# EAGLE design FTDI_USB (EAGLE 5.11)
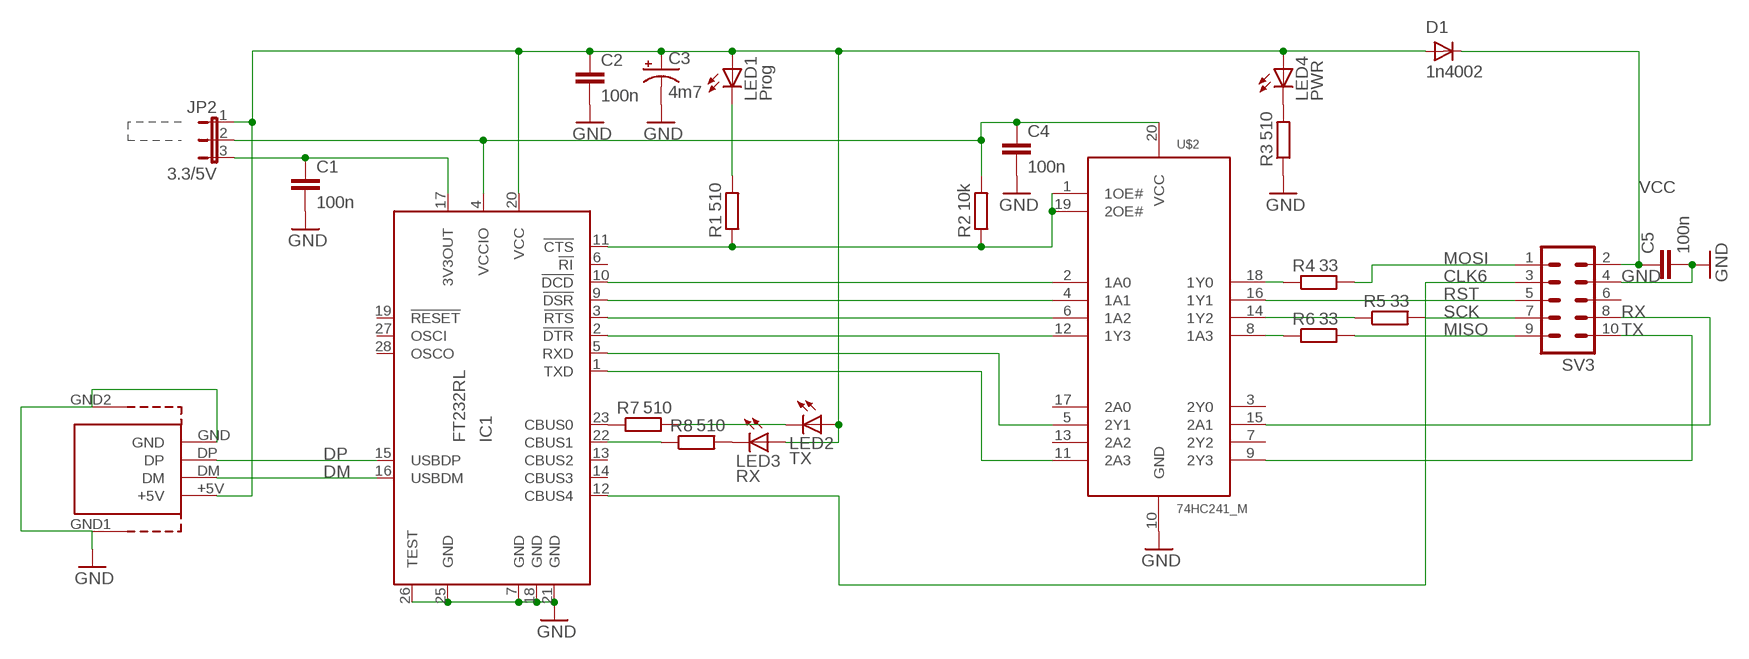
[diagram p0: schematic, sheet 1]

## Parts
C1  100n  C-EUC1206  [C1206]
C2  100n  C-EUC1206  [C1206]
C3  4m7  CPOL-USSMCD  [SMC_D]
C4  100n  C-EUC1206  [C1206]
C5  100n  C-EUC1206  [C1206]
D1  1n4002  GF1  [SMA-DO214AC]
IC1  FT232RL  [SSOP28]
JP2  3.3/5V  JP2E  [JP2]
LED1  Prog  LEDCHIPLED_1206  [CHIPLED_1206]
LED2  TX  LEDCHIPLED_1206  [CHIPLED_1206]
LED3  RX  LEDCHIPLED_1206  [CHIPLED_1206]
LED4  PWR  LEDCHIPLED_1206  [CHIPLED_1206]
R1  510  R-EU_M1206  [M1206]
R2  10k  R-EU_M1206  [M1206]
R3  510  R-EU_M1206  [M1206]
R4  33  R-EU_M1206  [M1206]
R5  33  R-EU_M1206  [M1206]
R6  33  R-EU_M1206  [M1206]
R7  510  R-EU_M1206  [M1206]
R8  510  R-EU_M1206  [M1206]
SV3  ML10  [ML10]
U$1  USB  [USB]
U$2  74HC241_M  [SO20W]

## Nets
CLK6: IC1.12(CBUS4) SV3.3
DM: IC1.16(USBDM) U$1.DM
DP: IC1.15(USBDP) U$1.DP
GND: C1.2 C2.2 C3.- C4.2 C5.2 IC1.7(GND) IC1.18(GND) IC1.21(GND) IC1.25(GND) IC1.26(TEST) R3.1 SV3.4 U$1.GND U$1.GND1 U$1.GND2 U$2.10(GND)
MISO: R6.2 SV3.9
MOSI: R4.2 SV3.1
N$1: IC1.10(!DCD) U$2.2(1A0)
N$2: IC1.9(!DSR) U$2.4(1A1)
N$3: IC1.3(!RTS) U$2.6(1A2)
N$4: IC1.2(!DTR) U$2.12(1Y3)
N$5: IC1.5(RXD) U$2.5(2Y1)
N$6: IC1.1(TXD) U$2.11(2A3)
N$7: IC1.11(!CTS) R1.1 R2.1 U$2.1(1OE#) U$2.19(2OE#)
N$8: C2.1 C3.+ D1.A IC1.20(VCC) JP2.1 LED1.A LED2.A LED3.A LED4.A U$1.+5V
N$9: C1.1 IC1.17(3V3OUT) JP2.3
N$10: C4.1 IC1.4(VCCIO) JP2.2 R2.2 U$2.20(VCC)
N$11: LED1.C R1.2
N$12: LED2.C R7.2
N$13: LED3.C R8.2
N$14: IC1.23(CBUS0) R7.1
N$15: IC1.22(CBUS1) R8.1
N$16: LED4.C R3.2
N$17: R6.1 U$2.8(1A3)
N$18: R5.1 U$2.14(1Y2)
N$19: R4.1 U$2.18(1Y0)
RST: SV3.5 U$2.16(1Y1)
RX: SV3.8 U$2.15(2A1)
SCK: R5.2 SV3.7
TX: SV3.10 U$2.9(2Y3)
VCC: C5.1 D1.K(C) SV3.2
Unconnected: IC1.6(!RI) IC1.13(CBUS2) IC1.14(CBUS3) IC1.19(!RESET) IC1.27(OSCI) IC1.28(OSCO) SV3.6 U$2.3(2Y0) U$2.7(2Y2) U$2.13(2A2) U$2.17(2A0)

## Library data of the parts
C1 C2 C4 C5 = resistor:C-EU: CAPACITOR, European symbol
C3 = rcl:CPOL-US: POLARIZED CAPACITOR, American symbol
D1 = diode:GF1: DIODE
IC1 = ftdichip_m:FT232R: Source: http://www.ftdichip.com/Documents/DataSheets/DS_FT232R_v104.pdf; MPN: FT232RL; OC_FARNELL: 1146032; OC_NEWARK: 91K9918
JP2 = jumper:JP2E: JUMPER
LED1-LED4 = led:LED: LED
R1-R8 = resistor:R-EU_: RESISTOR, European symbol
SV3 = con-ml:ML10: HARTING; OC_FARNELL: unknown; OC_NEWARK: unknown
U$1 = USB:USB
U$2 = 74xx-eu:74HC241_M

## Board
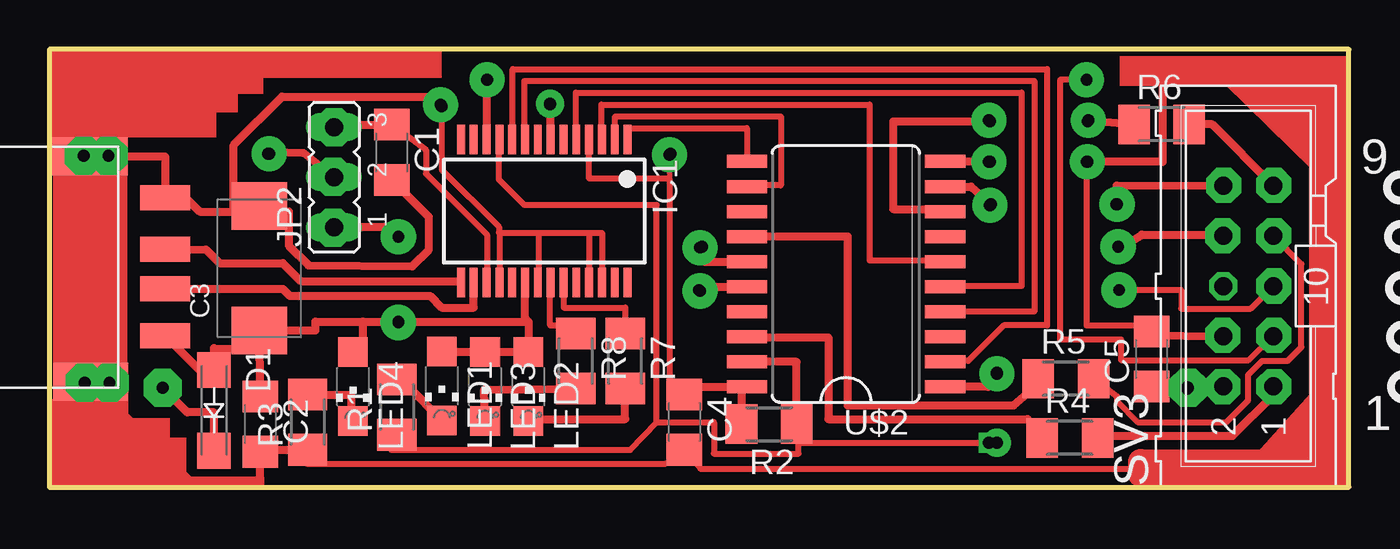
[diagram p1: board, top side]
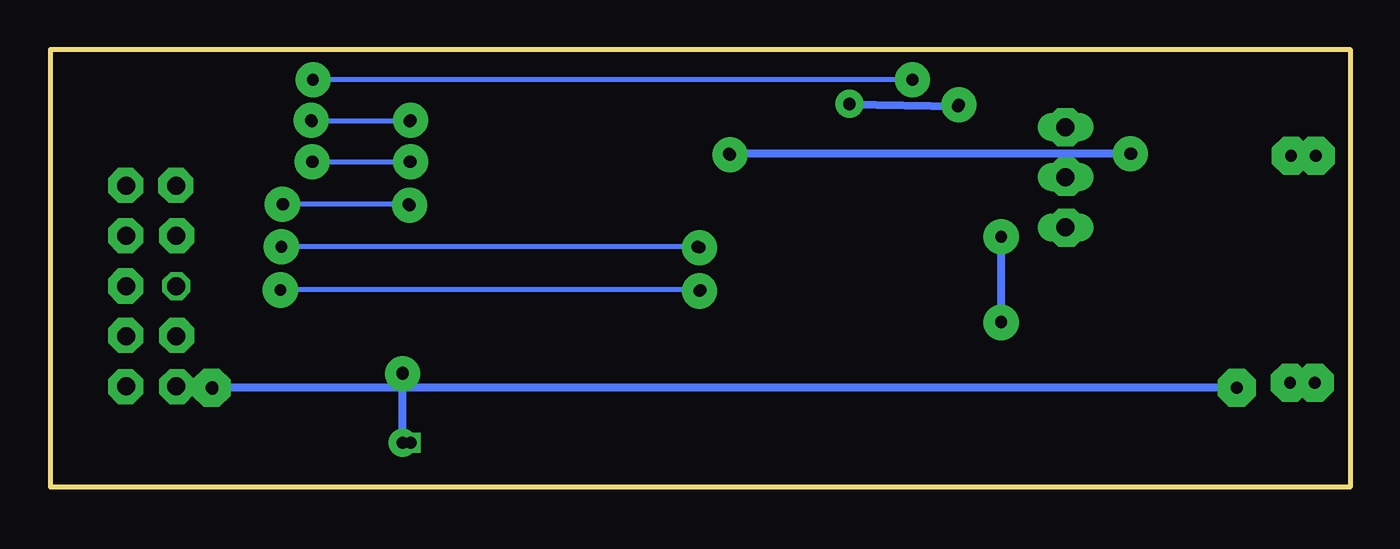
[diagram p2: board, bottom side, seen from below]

Size 65.9 x 22.2 mm. Coordinates in mm from the lower left corner, seen from the top.
Outline: 0,0 65.9,0 65.9,22.2 0,22.2 0,0
Copper layers (1*16): Top 0.035mm / dielectric 1.5mm / Bottom 0.035mm
Design rules "default": minimum track width 10mil, minimum drill 24mil, track to track 8mil, track to pad 8mil, pad to pad 8mil, via to via 8mil, smd to smd 8mil, copper to edge 40mil, drill to drill 8mil, minimum pad ring 10mil, minimum via ring 8mil, stop-mask expansion 4mil, vias tented up to drill 0mil, thermal gap 10mil

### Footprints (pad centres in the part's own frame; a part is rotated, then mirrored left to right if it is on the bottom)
C1206 = smd 1.6 x 1.8: 1 -1.4,0; 2 1.4,0
SMC_D = smd 2.4 x 2.8: + -3.15,0; - 3.15,0
SMA-DO214AC = smd 1.8 x 1.7: A -2.05,0; K 2.05,0
SSOP28 = smd 0.4 x 1.5: 1 -4.225,-3.625; 2 -3.575,-3.625; 3 -2.925,-3.625; 4 -2.275,-3.625; 5 -1.625,-3.625; 6 -0.975,-3.625; 7 -0.325,-3.625; 8 0.325,-3.625; 9 0.975,-3.625; 10 1.625,-3.625; 11 2.275,-3.625; 12 2.925,-3.625; 13 3.575,-3.625; 14 4.225,-3.625; 15 4.225,3.625; 16 3.575,3.625; 17 2.925,3.625; 18 2.275,3.625; 19 1.625,3.625; 20 0.975,3.625; 21 0.325,3.625; 22 -0.325,3.625; 23 -0.975,3.625; 24 -1.625,3.625; 25 -2.275,3.625; 26 -2.925,3.625; 27 -3.575,3.625; 28 -4.225,3.625
JP2 = drill 0.914 long: 1 -2.54,0; 2 0,0; 3 2.54,0
CHIPLED_1206 = smd 1.5 x 1.5: A 0,-1.75; C 0,1.75
M1206 = smd 1.6 x 2: 1 -1.4,0; 2 1.4,0
ML10 = drill 0.914 octagon: 1 -5.08,-1.27; 2 -5.08,1.27; 3 -2.54,-1.27; 4 -2.54,1.27; 5 0,-1.27; 6 0,1.27; 7 2.54,-1.27; 8 2.54,1.27; 9 5.08,-1.27; 10 5.08,1.27
USB = smd 2.54 x 1.27: +5V 6.78,-3.27; DM 6.78,-0.895; DP 6.78,1.11; GND 6.78,3.715 | smd 3.81 x 1.93: GND1 3.005,-5.61; GND2 2.97,5.82
SO20W = smd 0.66 x 2.032: 1 -5.715,-5.029; 2 -4.445,-5.029; 3 -3.175,-5.029; 4 -1.905,-5.029; 5 -0.635,-5.029; 6 0.635,-5.029; 7 1.905,-5.029; 8 3.175,-5.029; 9 4.445,-5.029; 10 5.715,-5.029; 11 5.715,5.029; 12 4.445,5.029; 13 3.175,5.029; 14 1.905,5.029; 15 0.635,5.029; 16 -0.635,5.029; 17 -1.905,5.029; 18 -3.175,5.029; 19 -4.445,5.029; 20 -5.715,5.029

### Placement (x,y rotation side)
C1  17.36,16.98 270 top
C2  10.7,3.2 270 top
C3  10.65,11.1 90 top
C4  32.2,3.3 270 top
C5  55.9,6.5 90 top
D1  8.35,3.9 270 top
IC1  25.1,14 180 top
JP2  14.44,15.72 90 top
LED1  19.9,5.14 180 top
LED2  24.3,5.1 180 top
LED3  22.1,5.1 180 top
LED4  15.4,5.1 180 top
R1  17.64,4.06 90 top
R2  36.5,3.2 180 top
R3  13.1,3.3 90 top
R4  51.75,2.5 0 top
R5  51.55,5.5 0 top
R6  56.4,18.4 0 top
R7  29.2,6.4 270 top
R8  26.7,6.4 270 top
SV3  60.8,10.2 90 top
U$1  -0.91,10.95 0 top
U$2  40.4,10.8 90 top

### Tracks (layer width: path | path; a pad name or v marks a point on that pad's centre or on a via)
CLK6  (via drill 0.6 pad 1.78)
  Top 0.254: IC1.12 22.2,18.02
  Top 0.305: SV3.3 60.82,6.45 54.35,6.45 54.35,7.5 51.25,7.5 51.25,20.65 v52.6,20.65
  Top 0.406: 22.2,18.02 v22.2,20.65
  Bottom 0.254: v22.2,20.65 v52.6,20.65
DM
  Top 0.406: U$1.DM 11.84,10.06 12.2,9.7 19.3,9.7 19.9,9.1 21.53,9.1 IC1.16
DP
  Top 0.254: U$1.DP 5.9,12.1
  Top 0.406: IC1.15 20.88,10.45 12.75,10.45 11.83,11.37 8.64,11.37 7.95,12.05 5.9,12.1
GND  (via drill 0.6, 0.6 pad 1.78)
  Top 0.254: IC1.25 27.4,10.77 27.4,12.9 | 24.8,10.77 IC1.21 | 25.4,18.12 IC1.7 | 31.25,1.2 C4.2 33,0.95 | R3.1 13.05,1.2 | 45.43,16.5 U$2.10 | v47.7,16.5 v47.65,16.5 | v52.65,16.5 v52.6,16.5 | 56.45,20.5 59.7,20.5 64.1,16.2 64.1,4.9 63.85,1.2 56.65,0.8 54.8,0.95 | 55.2,8.2 C5.2 | 9.35,13.97 10.7,13.97 | 7,14.6 5.94,14.6 U$1.GND | 10,2.4 10.9,1.5 10.9,2 C2.2 | 22.8,12.92 22.82,12.9
  Top 0.305: 24.8,12.9 27.38,12.9 IC1.25 | 27.4,12.9 28.03,12.9 IC1.26 | 24.8,12.9 24.8,10.77 | IC1.18 22.82,12.9 24.8,12.9 | 13.05,1.2 31.25,1.2 | v52.6,16.5 52.6,8.2 55.2,8.2 | 33,0.95 54.8,0.95 | 22.8,12.92 22.8,13.2 19.9,16.1 v19.9,19.3
  Top 0.406: 2.1,16.77 U$1.GND2 | 2.1,16.77 U$1.GND1 7.09,0.35 10.7,0.35 C2.2 11.1,1.8 11,1.9 R3.1 | 2.1,16.77 5.87,16.77 U$1.GND | C3.- 10.7,13.97 12.15,13.97 12.15,12.25 13.15,11.25 18.4,11.2 19.25,12.05 19.25,13.69 C1.2 | v25.4,19.4 25.4,18.12 | v19.9,19.3 19.9,19.8 11.8,19.8 9.35,17.35 9.35,13.97 7.63,13.97 7,14.6 | C5.2 55.53,7.7 SV3.4 | v47.65,16.5 45.43,16.5 | v52.65,16.5 56.45,16.5 56.45,20.5
  Bottom 0.254: v52.6,16.5 v47.7,16.5
  Bottom 0.406: v19.9,19.3 v25.4,19.4
MISO
  Top 0.406: R6.2 58.97,18.4 SV3.9
MOSI
  Top 0.254: 62.07,4.67 SV3.1 | R4.2 52.7,2.6
  Top 0.406: 62.07,4.67 60,2.6 52.7,2.6
N$1
  Top 0.254: IC1.10 23.5,18.02 | 45.43,6.4 U$2.2
  Top 0.305: 23.5,18.02 23.5,21.2 50.6,21.2 50.6,8.2 48.4,8.2 46.6,6.4 45.43,6.4
N$2
  Top 0.254: IC1.9 24.1,18.02 | U$2.4
  Top 0.305: 24.1,18.02 24.1,20.6 49.95,20.6 49.95,8.9 U$2.4
N$3
  Top 0.254: IC1.3 28,18.02 | 45.43,11.5 U$2.6
  Top 0.305: 28,18.02 28,19.4 41.6,19.4 41.6,11.5 45.43,11.5
N$4
  Top 0.254: IC1.2 28.7,18.02 | 35.37,15.3 U$2.12
  Top 0.305: 28.7,18.02 28.7,18.8 37.1,18.8 37.1,15.3 35.37,15.3
N$5
  Top 0.254: IC1.5 26.7,18.12 | 45.43,10.2 U$2.5
  Top 0.305: 26.7,18.12 26.7,20 49.3,20 49.3,10.2 45.43,10.2
N$6
  Top 0.254: 29.35,18.2 29.35,17.62 IC1.1
  Top 0.305: U$2.11 35.37,18.2 29.35,18.2
N$7  (via drill 0.6, 0.6 pad 1.42)
  Top 0.254: 22.8,17.98 IC1.11 | 38,2.25 R2.1 | 17.35,1.9 17.64,2.23 R1.1
  Top 0.305: 22.8,17.98 22.8,15.6 24.1,14.3 30.8,14.3 30.8,3.3 | 30.8,3.3 33.7,3.3 33.7,1.7 38,1.7 38,2.25 v48.05,2.25 | 30.8,3.3 29.45,1.9 17.35,1.9
  Top 0.406: U$2.19 37.9,6.35 R2.1 | U$2.1 47.6,5.09 v48.05,5.8
  Bottom 0.406: v48.05,5.8 v48.05,2.25 v47.65,2.25
N$8  (via drill 0.6, 0.6 pad 1.78)
  Top 0.254: D1.A 8.3,5.35 | U$1.+5V 5.8,7.62
  Top 0.406: 10.65,7 C2.1 | 10.65,7 C3.+ 13.5,7.95 13.5,8.4 15.9,8.4 | 5.87,8.05 U$1.+5V 7.61,5.95 D1.A 8.35,7.05 10.65,7 | 15.9,8.4 v17.7,8.4 24.3,8.4 | IC1.20 24.13,8.6 24.3,8.4 | LED4.A 15.9,6.85 15.9,8.4 | 24.3,8.4 LED2.A LED3.A 19.5,6.85 LED1.A | JP2.1 17.7,13.17 v17.7,12.7
  Bottom 0.406: v17.7,8.4 v17.7,12.7
N$9
  Top 0.254: 22.2,10.77 IC1.17
  Top 0.305: 22.2,10.77 22.2,12.8 19.1,15.9 19.1,17.1 17.36,18.4
  Top 0.406: JP2.3 14.44,18.38 C1.1 17.36,18.4
N$10  (via drill 0.6)
  Top 0.254: IC1.4 27.4,18.02 | 31.45,16 31.45,15.65 | 35.37,5.1 U$2.20 35.1,5.09 | 31.45,5.1 32.5,5.1 C4.1
  Top 0.305: v31.5,16.9 31.45,16 | 31.45,5.1 31.45,15.65 27.38,15.65 IC1.4
  Top 0.406: JP2.2 12.89,16.95 11.25,17 v11.1,16.9 | 32.5,5.1 35.37,5.1 | 35.1,5.09 R2.2
  Bottom 0.406: v11.1,16.9 v31.5,16.9
N$11
  Top 0.254: 18.24,5.06 R1.2
  Top 0.406: LED1.C 18.24,5.06
N$12
  Top 0.406: R7.2 29.2,3.45 24.1,3.45 LED2.C
N$13
  Top 0.406: LED3.C 22.05,4.95 R8.2
N$14
  Top 0.254: 26.1,10.73 IC1.23
  Top 0.305: 26.1,10.73 26.1,9.1 29.2,9.1 R7.1
N$15
  Top 0.254: 25.4,10.73 IC1.22
  Top 0.305: 25.4,10.73 25.4,8.2 27.2,8.2
  Top 0.406: 27.2,8.2 R8.1
N$16
  Top 0.254: 15.3,3.35 LED4.C
  Top 0.406: 15.3,3.35 15.3,4.7 R3.2
N$17  (via drill 0.6, 0.6 pad 1.78)
  Top 0.254: U$2.8 45.58,13.98 44.55,14.1 | v52.65,18.55 v52.7,18.6
  Top 0.406: 44.55,14.1 42.8,14.1 42.8,18.55 v47.7,18.55 | v52.7,18.6 R6.1
  Bottom 0.254: v47.7,18.55 v52.65,18.55
N$18
  Top 0.254: 50.15,5.25 R5.1
  Top 0.406: 50.15,5.25 48.9,4.15 40.5,4.15 40.5,12.7 U$2.14
N$19
  Top 0.406: U$2.18 35.37,7.6 39.5,7.6 39.5,3.45 49.6,3.45 R4.1
N$20  (via drill 0.6 pad 1.78)
  other vias: 11.15,16.9
N$21  (via drill 0.6 pad 1.78)
  other vias: 19.85,19.4
N$22  (via drill 0.6 pad 1.42)
  other vias: 25.4,19.45
N$23  (via drill 0.6 pad 1.78)
  other vias: 31.45,16.85
N$24  (via drill 0.6 pad 1.78)
  other vias: 17.7,8.35
N$25  (via drill 0.6 pad 1.78)
  other vias: 33,12.15
N$26  (via drill 0.6 pad 1.78)
  other vias: 33,9.95
N$27  (via drill 0.6 pad 1.78)
  other vias: 54.2,12.2
N$28  (via drill 0.6 pad 1.78)
  other vias: 54.25,10
N$29  (via drill 0.6 pad 1.78)
  other vias: 47.7,14.3
N$30  (via drill 0.6 pad 1.78)
  other vias: 54.15,14.35
N$31  (via drill 0.6 pad 1.78)
  other vias: 47.65,18.6
N$32  (via drill 0.6 pad 1.78)
  other vias: 48.05,5.75
N$34  (via drill 0.6 pad 1.78)
  other vias: 57.7,5
N$35  (via drill 0.7 pad 1.78)
  other vias: 59.55,15.3
N$36  (via drill 0.7 pad 1.78)
  other vias: 62.1,15.3
N$37  (via drill 0.7 pad 1.78)
  other vias: 62.1,12.75
N$38  (via drill 0.7 pad 1.78)
  other vias: 59.5,12.75
N$39  (via drill 0.7 pad 1.78)
  other vias: 62.1,10.2
N$40  (via drill 0.7 pad 1.78)
  other vias: 62.1,7.7
N$41  (via drill 0.7 pad 1.78)
  other vias: 59.5,7.7
N$42  (via drill 0.7 pad 1.78)
  other vias: 59.5,5.1
N$43  (via drill 0.7 pad 1.78)
  other vias: 62.1,5.1
N$44  (via drill 0.6 pad 1.93)
  other vias: 14.45,18.25
N$45  (via drill 0.6 pad 1.93)
  other vias: 14.4,15.75
N$46  (via drill 0.6 pad 1.93)
  other vias: 14.4,13.15
N$47  (via drill 0.6 pad 1.93)
  other vias: 1.75,16.8
N$48  (via drill 0.6 pad 1.93)
  other vias: 3,16.8
N$49  (via drill 0.6 pad 1.93)
  other vias: 3.05,5.3
N$50  (via drill 0.6 pad 1.93)
  other vias: 1.8,5.3
N$51
  Top 1.27: 60.5,20.75 60.5,20.65 64.25,16.9 64.25,18.45 64.7,18.9 63.4,18.9 63.35,18.85
N$52
  Top 1.27: 64.65,4.65 64.65,4.6 61.7,1.3 55.35,1.3 55.35,0.65 61.65,0.65 62.75,1.75 64.3,1.75
RST  (via drill 0.6)
  Top 0.254: v32.95,10 33.1,10.16
  Top 0.305: v54.25,10 57.4,10 57.4,9.05 60.92,9.05 SV3.5
  Top 0.406: 33.1,10.16 U$2.16
  Bottom 0.254: v32.95,10 v54.25,10
RX  (via drill 0.6)
  Top 0.254: v54.2,12.2 54.35,12.15 | 59.53,12.8 SV3.8
  Top 0.406: U$2.15 33.2,11.44 v33.1,12.2 | 54.35,12.15 55.4,12.8 59.53,12.8
  Bottom 0.254: v33.1,12.2 v54.2,12.2
SCK
  Top 0.254: R5.2 53,4.85
  Top 0.305: R5.2 54.15,4.6 54.15,4.35 55.2,3.3 59.7,3.3 60.8,4.4 60.8,5.7 61.5,6.4 62.8,6.4 63.5,7.1 63.5,11.31 SV3.7
TX  (via drill 0.6)
  Top 0.254: v54.1,14.35 54.13,15.3
  Top 0.406: U$2.9 46.75,15.24 v47.75,14.35 | 54.13,15.3 SV3.10
  Bottom 0.254: v47.75,14.35 v54.1,14.35
VCC  (via drill 0.6, 0.6 pad 1.93)
  Top 0.254: 55.58,5 C5.1
  Top 0.406: SV3.2 v57.7,5.07 57,5.12 C5.1 | 55.58,5 56.13,5.05 v57.75,5.05 | v5.75,5.05 7,3.8 8.35,3.8 D1.K
  Bottom 0.406: v5.75,5.05 v57.75,5.05
(copper drawn outside any net)
  shapes: Top area x24

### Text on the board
tPlace: 1 - VCC | 2 - MOSI | 9 | 10 | 3 - GND | 4 - CLK | 5 | 6 - RST | 7 - RX | 8 - SCK | 1 | 2 | 9 - TX | 10 - MISO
